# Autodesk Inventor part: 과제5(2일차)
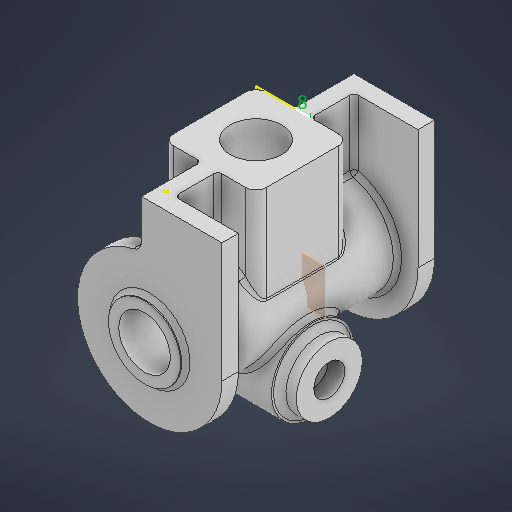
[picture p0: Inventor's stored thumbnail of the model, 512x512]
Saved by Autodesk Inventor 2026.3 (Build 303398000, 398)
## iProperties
Created: 2026-08
Part Number: 과제5(2일차)
Material: 일반
Document SubType Name: Modeling
Designer: chang
Density: 1 g/cm^3
Appearance: 기본값
Author: chang
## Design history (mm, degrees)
sketch "스케치1"
  geometry: L1 (35, 0)-(35, 58); L2 (35, 58)-(-4, 58); L3 (-4, 58)-(-4, 38.974); C1 r 12.5 at (0, 0); A1 r 35 centre (0, 0) between (-7.875, 34.103) and (35, 0); A2 r 5 centre (-9, 38.974) between (-7.875, 34.103) and (-4, 38.974); 2 further points
  constraints: 6 end point, 5 point on circle, 3 centre point, 3 tangent, 2 perpendicular, 1 coincident, 1 point on line, 1 vertical
  dimensions: "d0" = 70 diameter of A1; "d2" = 58 distance of L1.start L1.end; "d3" = 39 distance of L1.end L2.end; "d4" = 5 radius of A2 (derived); "d6" = 25 diameter of C1
extrude "돌출1" new body sketch "스케치1" distance "d7" = 8; taper "d8" = 0 deg
sketch "스케치2"
  geometry: C1 r 17.5 at (0, 0); C2 r 12.5 at (0, 0); 1 further point
  constraints: 2 centre point, 2 coincident
  dimensions: "d9" = 35 diameter of C1
extrude "돌출2" join sketch "스케치2" distance "d10" = 2.5; taper "d11" = 0 deg
sketch "스케치3"
  geometry: L1 (4, 58)-(4, 38.974) reference; L2 (4, 58)-(-4, 58); L3 (-35, 58)-(4, 58) reference; L4 (-4, 58)-(-4, 20); L5 (-4, 20)-(4, 20); L6 (4, 20)-(4, 58); 2 further points
  constraints: 8 end point, 1 collinear, 1 perpendicular, 1 point on line, 1 vertical
  dimensions: "d12" = 8 distance of L1.start L2.end; "d13" = 38 distance of L2.end L4.end
extrude "돌출3" join sketch "스케치3" distance "d14" = 21; taper "d15" = 0 deg
sketch "스케치4"
  geometry: C1 r 25 at (0, 0); C2 r 12.5 at (0, 0); 1 further point
  constraints: 2 centre point, 2 coincident
  dimensions: "d16" = 50 diameter of C1
extrude "돌출4" join sketch "스케치4" distance "d17" = 87; taper "d18" = 0 deg
sketch "스케치5"
  geometry: L1 (0, 29)-(0, 0) reference; L2 (0, 29)-(-18.5, 29); L3 (-18.5, 29)-(-18.5, 74); L4 (-18.5, 74)-(26.5, 74); L5 (26.5, 74)-(26.5, 29); L6 (26.5, 29)-(-18.5, 29); C1 r 12.5 at (4, 51.5); 2 further points
  constraints: 10 end point, 4 perpendicular, 1 centre point, 1 horizontal, 1 point on line
  dimensions: "d19" = 18.5 distance of L1.start L2.end; "d20" = 45 distance of L2.end L3.end; "d21" = 45 distance of L3.end L4.end; "d22" = 25 diameter of C1
extrude "돌출5" join sketch "스케치5" distance "d23" = 50; taper "d24" = 0 deg
sketch "스케치6"
  geometry: L1 (45, 0)-(45, -47.103) reference; L2 (45, 0)-(26.5, 0) reference; L3 (45, 0)-(26.5, 0); L4 (26.5, 0)-(18.5, 0); 1 further point
  constraints: 4 end point, 1 collinear, 1 point on line
  dimensions: "d25" = 8 distance of L2.end L4.end
sketch "스케치7"
  geometry: 1 further point
sketch "스케치8"
  geometry: L1 (26.5, 74)-(-18.5, 74) reference; L2 (0, 74)-(8, 74); L3 (8, 74)-(8, 95); L4 (8, 95)-(0, 95); L5 (0, 95)-(0, 74); 1 further point
  constraints: 8 end point, 3 perpendicular, 2 point on line
  dimensions: "d26" = 8 distance of L2.start L2.end; "d27" = 21 distance of L2.end L3.end
extrude "돌출6" join sketch "스케치8" distance "d28" = 50; taper "d29" = 0 deg
sketch "스케치9"
  geometry: C1 r 12.5 at (0, 0) reference; A1 r 12.5 centre (0, 0) between (-4, 11.843) and (4, 11.843) reference; 1 further point
  constraints: 1 centre point, 1 coincident, 1 other
sketch "스케치10"
  geometry: 1 further point
sketch "스케치11"
  geometry: L1 (4, 58)-(4, 24.678) reference; L2 (4, 38.974)-(4, 58); L3 (4, 58)-(-35, 58); L4 (-35, 58)-(-35, 0); A1 r 5 centre (9, 38.974) between (4, 38.974) and (7.875, 34.103) reference; A2 r 35 centre (0, 0) between (-35, 0) and (7.875, 34.103); A3 r 5 centre (9, 38.974) between (4, 38.974) and (7.875, 34.103); 2 further points
  constraints: 6 end point, 6 point on circle, 3 tangent, 2 centre point, 2 point on line, 1 coincident, 1 collinear
  dimensions: "d30" = 5 radius of A3 (derived)
sketch "스케치12"
  geometry: 1 further point
sketch "스케치13"
  geometry: 1 further point
extrude "돌출7" join sketch "스케치11" distance "d31" = 8; taper "d32" = 0 deg
sketch "스케치14"
  geometry: C1 r 12.5 at (0, 0); 1 further point
  constraints: 1 centre point, 1 coincident
  dimensions: "d33" = 25 diameter of C1
extrude "돌출8" cut sketch "스케치14" distance "d34" = 110; taper "d35" = 0 deg
sketch "스케치15"
  geometry: 1 further point
sketch "스케치16"
  geometry: 1 further point
node "작업 평면1"
sketch "스케치17"
  geometry: 1 further point
sketch "스케치18"
  geometry: 1 further point
sketch "스케치19"
  geometry: 1 further point
sketch "스케치20"
  geometry: L1 (-21, -83)-(66, -83) reference; C1 r 20 at (22.5, -83); C2 r 16 at (22.5, -83); 1 further point
  constraints: 2 centre point, 1 coincident, 1 midpoint
  dimensions: "d36" = 40 diameter of C1; "d37" = 32 diameter of C2
extrude "돌출9" join sketch "스케치20" distance "d38" = 50; taper "d39" = 0 deg
sketch "스케치21"
  geometry: 1 further point
sketch "스케치22"
  geometry: 1 further point
sketch "스케치23"
  geometry: L1 (-21, -83)-(66, -83) reference; C1 r 16 at (22.5, -83); 3 further points
  constraints: 1 centre point, 1 midpoint
extrude "돌출10" cut sketch "스케치23" distance "d40" = 66; taper "d41" = 0 deg
sketch "스케치24"
  geometry: C1 r 16 at (22.5, -83) reference; C2 r 16 at (22.5, -83); C3 r 20 at (22.5, -83); 1 further point
  constraints: 2 centre point, 2 coincident
  dimensions: "d43" = 40 diameter of C3
extrude "돌출11" join sketch "스케치24" distance "d44" = 5; taper "d45" = 0 deg
sketch "스케치25"
  geometry: C1 r 7.5 at (0, 0); A1 r 16 centre (0, 0) between (7.557, 14.103) and (-7.557, 14.103) reference; 3 further points
  constraints: 1 centre point, 1 coincident, 4 other
  dimensions: "d46" = 15 diameter of C1
extrude "돌출12" join sketch "스케치25" distance "d47" = 8; taper "d48" = 0 deg
sketch "스케치26"
  geometry: 1 further point
sketch "스케치27"
  geometry: C1 r 16 at (0, 0); C2 r 7.5 at (0, 0); 1 further point
  constraints: 2 centre point, 1 coincident, 1 other
  dimensions: "d49" = 32 diameter of C1; "d50" = 15 diameter of C2
extrude "돌출13" join sketch "스케치27" distance "d51" = 8; taper "d52" = 0 deg
feature "면 모깎기1" dims "d53" = 3
feature "면 모깎기2" dims "d54" = 3
fillet "모깎기1" dims "d55" = 5
fillet "모깎기2" dims "d56" = 5
fillet "모깎기3" dims "d57" = 5
fillet "모깎기4" dims "d58" = 5
sketch "스케치28"
  geometry: C1 r 12.5 at (0, 0); C2 r 17.5 at (0, 0); 1 further point
  constraints: 2 centre point, 2 coincident
  dimensions: "d59" = 25 diameter of C1; "d60" = 35 diameter of C2
extrude "돌출14" join sketch "스케치28" distance "d61" = 2.5; taper "d62" = 0 deg
feature "면 모깎기3" dims "d63" = 2
feature "면 모깎기4" dims "d64" = 2
feature "면 모깎기5" dims "d65" = 2
feature "면 모깎기6" dims "d66" = 2
feature "면 모깎기7" dims "d67" = 2
feature "면 모깎기8" dims "d68" = 2
feature "면 모깎기9" dims "d69" = 2
feature "면 모깎기10" dims "d70" = 2
feature "면 모깎기11" dims "d71" = 2
feature "면 모깎기12" dims "d72" = 2
feature "면 모깎기13" dims "d73" = 2
node "솔리드1"
